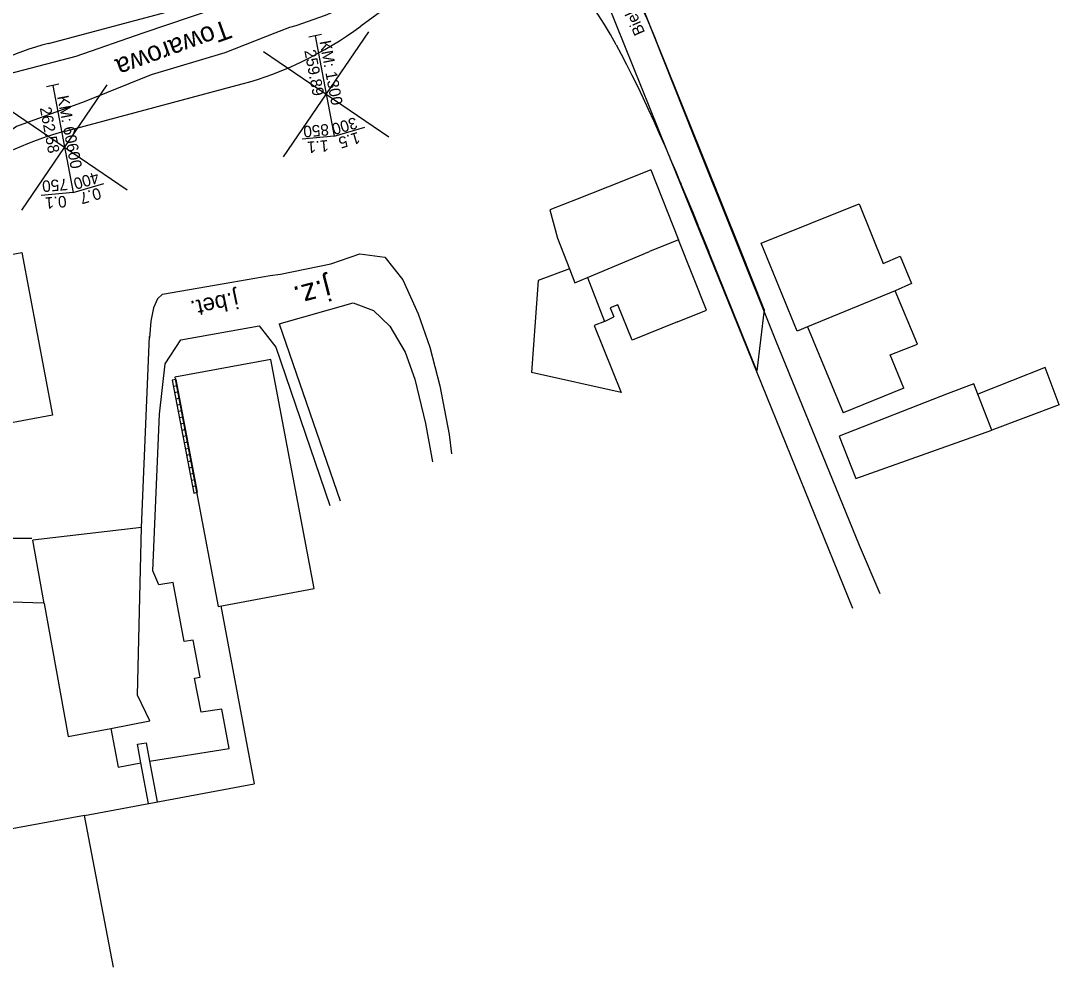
# Model space of a CAD drawing. Extents: x 6541740 to 6566395, y 5525066 to 5530361.
# Drawn here: x 6564401.8 to 6564483.2, y 5527760.2 to 5527834.5 of the extents above; entities that cross this region are included whole.
import ezdxf

# ---------------------------------------------------------------- set-up
doc = ezdxf.new("R2010")
doc.units = 0
for name, color, linetype in [('Domyślna', 7, 'Continuous'), ('ps_wymiarowanie', 7, 'Continuous'), ('TOR_PRZEK_P-teren istniejacy', 7, 'Continuous'), ('TOR_PRZEK_P-uklad odniesienia', 7, 'Continuous'), ('TOR_PS_ODW-osadniki', 7, 'Continuous'), ('TOR_PS_OPIS_T-symbole geometrii', 7, 'Continuous')]:
    doc.layers.add(name, color=color, linetype=linetype)

msp = doc.modelspace()

# ---------------------------------------------------------------- linework, layer by layer
at = {"layer": 'Domyślna'}
msp.add_line((6564469.13, 5527789.53), (6564469.13, 5527789.53), dxfattribs=at)
at = {"layer": 'ps_wymiarowanie'}
for p, q in [((6564452.38, 5527824.419), (6564466.999, 5527788.383)), ((6564451.179, 5527822.778), (6564448.904, 5527821.858)), ((6564451.179, 5527822.778), (6564453.357, 5527817.265)), ((6564451.179, 5527822.778), (6564453.357, 5527817.265)), ((6564448.904, 5527821.858), (6564445.393, 5527820.47)), ((6564448.904, 5527821.858), (6564445.393, 5527820.47)), ((6564445.393, 5527820.47), (6564443.266, 5527819.633)), ((6564445.393, 5527820.47), (6564443.266, 5527819.633)), ((6564459.829, 5527817.011), (6564467.516, 5527820.089)), ((6564459.829, 5527817.011), (6564467.516, 5527820.089)), ((6564467.516, 5527820.089), (6564469.377, 5527815.415)), ((6564467.516, 5527820.089), (6564469.377, 5527815.415)), ((6564443.266, 5527819.633), (6564443.872, 5527817.407)), ((6564443.266, 5527819.633), (6564443.872, 5527817.407)), ((6564443.872, 5527817.407), (6564444.8, 5527815.008)), ((6564443.872, 5527817.407), (6564444.8, 5527815.008)), ((6564453.357, 5527817.265), (6564451.081, 5527816.359)), ((6564453.357, 5527817.265), (6564451.081, 5527816.359)), ((6564455.539, 5527811.75), (6564453.357, 5527817.265)), ((6564462.661, 5527810.122), (6564459.829, 5527817.011)), ((6564446.213, 5527814.319), (6564451.081, 5527816.359)), ((6564446.213, 5527814.319), (6564451.081, 5527816.359)), ((6564469.377, 5527815.415), (6564470.71, 5527815.99)), ((6564469.377, 5527815.415), (6564470.71, 5527815.99)), ((6564470.71, 5527815.99), (6564471.603, 5527813.856)), ((6564470.71, 5527815.99), (6564471.603, 5527813.856)), ((6564444.8, 5527815.008), (6564442.35, 5527814.099)), ((6564444.8, 5527815.008), (6564442.35, 5527814.099)), ((6564444.8, 5527815.008), (6564445.226, 5527813.907)), ((6564444.8, 5527815.008), (6564445.226, 5527813.907)), ((6564445.226, 5527813.907), (6564446.213, 5527814.319)), ((6564445.226, 5527813.907), (6564446.213, 5527814.319)), ((6564446.213, 5527814.319), (6564447.549, 5527810.875)), ((6564446.213, 5527814.319), (6564447.549, 5527810.875)), ((6564442.35, 5527814.099), (6564441.822, 5527806.879)), ((6564442.35, 5527814.099), (6564441.822, 5527806.879)), ((6564471.603, 5527813.856), (6564470.331, 5527813.282)), ((6564471.603, 5527813.856), (6564470.331, 5527813.282)), ((6564470.331, 5527813.282), (6564463.468, 5527810.45)), ((6564470.331, 5527813.282), (6564463.468, 5527810.45)), ((6564472.09, 5527809.106), (6564470.331, 5527813.282)), ((6564472.09, 5527809.106), (6564470.331, 5527813.282)), ((6564448.597, 5527812.186), (6564448.002, 5527811.95)), ((6564448.597, 5527812.186), (6564448.002, 5527811.95)), ((6564448.002, 5527811.95), (6564448.286, 5527811.243)), ((6564448.002, 5527811.95), (6564448.286, 5527811.243)), ((6564449.704, 5527809.414), (6564448.597, 5527812.186)), ((6564449.704, 5527809.414), (6564448.597, 5527812.186)), ((6564447.549, 5527810.875), (6564448.286, 5527811.243)), ((6564447.549, 5527810.875), (6564448.286, 5527811.243)), ((6564453.256, 5527810.841), (6564455.539, 5527811.75)), ((6564447.549, 5527810.875), (6564446.744, 5527810.555)), ((6564447.549, 5527810.875), (6564446.744, 5527810.555)), ((6564446.744, 5527810.555), (6564448.851, 5527805.292)), ((6564446.744, 5527810.555), (6564448.851, 5527805.292)), ((6564453.256, 5527810.841), (6564449.704, 5527809.414)), ((6564453.256, 5527810.841), (6564449.704, 5527809.414)), ((6564463.468, 5527810.45), (6564462.661, 5527810.122)), ((6564463.468, 5527810.45), (6564462.661, 5527810.122)), ((6564463.468, 5527810.45), (6564466.25, 5527803.707)), ((6564463.468, 5527810.45), (6564466.25, 5527803.707)), ((6564411.244, 5527794.706), (6564411.883, 5527809.705)), ((6564469.935, 5527808.264), (6564472.09, 5527809.106)), ((6564469.935, 5527808.264), (6564472.09, 5527809.106)), ((6564421.39, 5527807.883), (6564413.875, 5527806.498)), ((6564424.781, 5527789.923), (6564421.39, 5527807.883)), ((6564471.012, 5527805.65), (6564469.935, 5527808.264)), ((6564482.092, 5527807.257), (6564476.821, 5527805.165)), ((6564483.191, 5527804.325), (6564482.092, 5527807.257)), ((6564413.875, 5527806.498), (6564417.275, 5527788.524)), ((6564448.851, 5527805.292), (6564441.822, 5527806.879)), ((6564448.851, 5527805.292), (6564441.822, 5527806.879)), ((6564414.052, 5527805.839), (6564413.757, 5527805.774)), ((6564414.146, 5527805.348), (6564413.851, 5527805.283)), ((6564471.012, 5527805.65), (6564466.25, 5527803.707)), ((6564471.012, 5527805.65), (6564466.25, 5527803.707)), ((6564476.506, 5527805.972), (6564474.498, 5527805.22)), ((6564476.506, 5527805.972), (6564474.498, 5527805.22)), ((6564476.821, 5527805.165), (6564476.506, 5527805.972)), ((6564414.24, 5527804.856), (6564413.945, 5527804.791)), ((6564474.498, 5527805.22), (6564465.928, 5527801.886)), ((6564477.919, 5527802.347), (6564476.821, 5527805.165)), ((6564414.334, 5527804.364), (6564414.039, 5527804.299)), ((6564414.428, 5527803.873), (6564414.133, 5527803.808)), ((6564483.191, 5527804.325), (6564477.919, 5527802.347)), ((6564414.523, 5527803.381), (6564414.227, 5527803.316)), ((6564414.617, 5527802.89), (6564414.322, 5527802.824)), ((6564414.711, 5527802.398), (6564414.416, 5527802.333)), ((6564467.252, 5527798.553), (6564477.919, 5527802.347)), ((6564467.252, 5527798.553), (6564477.919, 5527802.347)), ((6564414.805, 5527801.906), (6564414.51, 5527801.841)), ((6564414.899, 5527801.415), (6564414.604, 5527801.35)), ((6564465.928, 5527801.886), (6564467.252, 5527798.553)), ((6564465.928, 5527801.886), (6564467.252, 5527798.553)), ((6564414.993, 5527800.923), (6564414.698, 5527800.858)), ((6564415.087, 5527800.431), (6564414.792, 5527800.366)), ((6564415.182, 5527799.94), (6564414.886, 5527799.875)), ((6564415.276, 5527799.448), (6564414.981, 5527799.383)), ((6564415.37, 5527798.957), (6564415.075, 5527798.891)), ((6564415.464, 5527798.465), (6564415.169, 5527798.4)), ((6564415.558, 5527797.973), (6564415.263, 5527797.908)), ((6564402.644, 5527793.843), (6564400.256, 5527793.861)), ((6564403.612, 5527788.761), (6564402.74, 5527793.722)), ((6564417.275, 5527788.524), (6564424.781, 5527789.923)), ((6564401.081, 5527788.886), (6564403.573, 5527788.798)), ((6564417.471, 5527788.562), (6564420.085, 5527774.618)), ((6564406.792, 5527772.143), (6564420.086, 5527774.62)), ((6564406.792, 5527772.143), (6564397.544, 5527770.416)), ((6564409.045, 5527760.231), (6564406.792, 5527772.143))]:
    msp.add_line(p, q, dxfattribs=at)
for points in [[(6564439.794, 5527862.198), (6564440.441, 5527860.533), (6564442.913, 5527854.409), (6564444.564, 5527850.278), (6564448.362, 5527841.013), (6564454.526, 5527825.454)], [(6564438.183, 5527857.453), (6564434.887, 5527851.935), (6564430.482, 5527845.184), (6564427.943, 5527841.388), (6564427.035, 5527840.06), (6564424.98, 5527838.436), (6564422.698, 5527837.597), (6564422.112, 5527838.024), (6564421.003, 5527836.715), (6564416.993, 5527835.393), (6564411.369, 5527833.475), (6564406.11, 5527831.665), (6564400.805, 5527830.27), (6564400.006, 5527831.003), (6564398.369, 5527830.331), (6564398.022, 5527829.118)], [(6564442.052, 5527846.843), (6564440.584, 5527846.148), (6564436.964, 5527844.435), (6564432.063, 5527839.361), (6564430.152, 5527837.611), (6564429.167, 5527836.71), (6564428.07, 5527835.923), (6564425.661, 5527834.868), (6564423.34, 5527834.06), (6564422.86, 5527833.93), (6564421.715, 5527833.479), (6564417.794, 5527831.947), (6564412.017, 5527830.217), (6564406.766, 5527828.095), (6564401.442, 5527826.16), (6564400.79, 5527825.697), (6564399.577, 5527825.279), (6564398.942, 5527824.749)], [(6564442.735, 5527845.857), (6564443.048, 5527845.79), (6564443.671, 5527845.657), (6564444.01, 5527845.228), (6564447.817, 5527835.764), (6564452.38, 5527824.419)], [(6564454.526, 5527825.454), (6564460.951, 5527809.402), (6564467.521, 5527793.32), (6564469.13, 5527789.53)], [(6564421.328, 5527814.474), (6564422.141, 5527814.582), (6564426.082, 5527815.404), (6564428.366, 5527816.183), (6564430.331, 5527815.926)], [(6564430.331, 5527815.926), (6564431.749, 5527814.143), (6564432.948, 5527811.464), (6564433.848, 5527808.87), (6564434.637, 5527805.829), (6564435.381, 5527802), (6564435.549, 5527800.49)], [(6564412.91, 5527813.025), (6564418.346, 5527813.953), (6564421.328, 5527814.474)], [(6564412.91, 5527813.025), (6564412.505, 5527812.656), (6564412.19, 5527811.938), (6564411.976, 5527810.899), (6564411.873, 5527809.579)], [(6564422.039, 5527810.68), (6564427.848, 5527812.342), (6564429.437, 5527811.737), (6564430.706, 5527810.504), (6564431.929, 5527808.468), (6564432.672, 5527806.34), (6564433.515, 5527802.869), (6564434.053, 5527799.856)], [(6564414.346, 5527809.437), (6564420.466, 5527810.545), (6564421.778, 5527808.866), (6564426.014, 5527796.452)], [(6564422.039, 5527810.68), (6564422.039, 5527810.68), (6564426.825, 5527796.796)], [(6564412.129, 5527791.31), (6564412.656, 5527803.608), (6564413.114, 5527807.556), (6564414.346, 5527809.437)], [(6564403.612, 5527788.761), (6564405.509, 5527778.329), (6564408.837, 5527778.965), (6564411.894, 5527779.548), (6564410.943, 5527781.561), (6564411.244, 5527794.706), (6564402.74, 5527793.722)], [(6564415.922, 5527780.225), (6564415.418, 5527782.914), (6564415.859, 5527782.983), (6564415.314, 5527785.886), (6564414.599, 5527785.774), (6564413.732, 5527790.398), (6564412.619, 5527790.223), (6564412.129, 5527791.31)], [(6564411.892, 5527776.404), (6564418.133, 5527777.388), (6564417.553, 5527780.482), (6564415.922, 5527780.225)], [(6564408.837, 5527778.965), (6564409.412, 5527775.93), (6564411.199, 5527776.271)], [(6564411.798, 5527773.076), (6564411.199, 5527776.271), (6564410.928, 5527777.714), (6564411.626, 5527777.824), (6564411.892, 5527776.404), (6564412.492, 5527773.205)]]:
    msp.add_lwpolyline(points, dxfattribs=at)
for points in [[(6564404.28, 5527803.533), (6564400.358, 5527802.789), (6564397.94, 5527815.547), (6564401.862, 5527816.291)], [(6564413.958, 5527806.331), (6564413.663, 5527806.266), (6564415.357, 5527797.417), (6564415.652, 5527797.482)]]:
    msp.add_lwpolyline(points, close=True, dxfattribs=at)
at = {"layer": 'TOR_PRZEK_P-uklad odniesienia'}
for p, q in [((6564422.384, 5527823.775), (6564429.074, 5527833.594)), ((6564430.639, 5527825.339), (6564420.819, 5527832.029)), ((6564401.868, 5527819.602), (6564408.558, 5527829.422)), ((6564410.122, 5527821.167), (6564400.303, 5527827.857))]:
    msp.add_line(p, q, dxfattribs=at)
at = {"layer": 'TOR_PS_ODW-osadniki'}
for p, q in [((6564425.353, 5527833.369), (6564424.371, 5527833.183)), ((6564424.862, 5527833.276), (6564426.351, 5527825.403)), ((6564404.784, 5527829.474), (6564403.803, 5527829.279)), ((6564404.294, 5527829.377), (6564405.885, 5527820.985)), ((6564426.351, 5527825.403), (6564428.761, 5527826.113)), ((6564426.351, 5527825.403), (6564423.848, 5527825.184)), ((6564405.885, 5527820.985), (6564408.295, 5527821.697)), ((6564405.885, 5527820.985), (6564403.383, 5527820.765))]:
    msp.add_line(p, q, dxfattribs=at)
at = {"layer": 'TOR_PS_OPIS_T-symbole geometrii'}
for p, q in [((6564435.57, 5527839.229), (6564428.445, 5527834.042)), ((6564403.953, 5527832.677), (6564417.799, 5527836.373)), ((6564456.317, 5527821.16), (6564451.92, 5527832.115)), ((6564405.288, 5527825.807), (6564419.134, 5527829.503)), ((6564456.735, 5527820.118), (6564455.429, 5527823.371)), ((6564458.226, 5527816.402), (6564456.735, 5527820.118)), ((6564459.48, 5527806.991), (6564455.733, 5527816.328)), ((6564460.064, 5527811.823), (6564458.226, 5527816.402)), ((6564460.064, 5527811.823), (6564459.48, 5527806.991))]:
    msp.add_line(p, q, dxfattribs=at)
for points in [[(6564448.466, 5527832.558), (6564448.849, 5527831.829), (6564449.273, 5527831.027), (6564449.699, 5527830.193), (6564450.125, 5527829.329), (6564450.553, 5527828.438), (6564450.981, 5527827.522), (6564451.41, 5527826.582), (6564451.84, 5527825.621), (6564452.271, 5527824.64), (6564452.643, 5527823.778)], [(6564452.643, 5527823.778), (6564452.702, 5527823.641), (6564453.134, 5527822.626), (6564453.489, 5527821.783)], [(6564453.498, 5527821.761), (6564453.567, 5527821.597), (6564454.001, 5527820.554), (6564454.436, 5527819.501), (6564454.862, 5527818.463)], [(6564454.862, 5527818.463), (6564454.872, 5527818.439), (6564455.31, 5527817.368), (6564455.733, 5527816.328)]]:
    msp.add_lwpolyline(points, dxfattribs=at)
for centre, major_axis, start_param, end_param in [((6564448.393, 5527795.626), (-8.511, 44.9), 5.62927, 6.150936), ((6564448.419, 5527803.121), (-8.381, 44.213), 5.37927, 5.625422), ((6564342.176, 5528225.53), (75.146, -396.441), 0.018415, 0.117751), ((6564480.912, 5527436.649), (-75.146, 396.441), 0.018415, 0.185981), ((6564480.912, 5527436.649), (-73.843, 389.563), 0.018415, 0.185981)]:
    msp.add_ellipse(centre, major_axis=major_axis, ratio=0.25, start_param=start_param, end_param=end_param, dxfattribs=at)

# ---------------------------------------------------------------- texts
at = {"layer": 'TOR_PRZEK_P-teren istniejacy'}
for s, height, rotation, p in [('Bielska', 0.8839, 113.89466, (6564450.74, 5527833.544)), ('Towarowa', 1.5216, 199.92406, (6564417.914, 5527834.587)), ('j.z.', 1.7102, 194.30176, (6564425.865, 5527814.268)), ('j.bet.', 1.3071, 191.86947, (6564418.701, 5527813.227))]:
    msp.add_text(s, height=height, rotation=rotation, dxfattribs=at).set_placement(p)
at = {"layer": 'TOR_PS_ODW-osadniki'}
for s, rotation, p in [('KM: 1300', 280.70811, (6564425.2, 5527832.831)), ('259.89', 280.74357, (6564424.011, 5527832.113)), ('KM: 60600', 280.7387, (6564404.639, 5527828.513)), ('262.58', 280.7387, (6564403.275, 5527827.619)), ('300', 196.4187, (6564428.012, 5527826.914)), ('850', 184.99751, (6564425.902, 5527826.371)), ('1.5', 196.4187, (6564428.219, 5527825.753)), ('1.1', 184.99751, (6564425.874, 5527825.111)), ('400', 196.4493, (6564407.766, 5527822.631)), ('750', 185.02811, (6564405.429, 5527822.085)), ('0.7', 196.4493, (6564407.923, 5527821.391)), ('0.1', 185.02811, (6564405.333, 5527820.744))]:
    msp.add_text(s, height=0.9, rotation=rotation, dxfattribs=at).set_placement(p)

doc.saveas('drawing.dxf')
